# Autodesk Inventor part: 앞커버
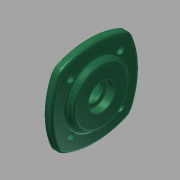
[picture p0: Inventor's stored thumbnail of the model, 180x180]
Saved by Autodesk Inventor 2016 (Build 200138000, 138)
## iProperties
Created: 2015-11
Part Number: 앞커버
Material: 일반
Document SubType Name: Modeling
Designer: mduedu
Density: 1 g/cm^3
Appearance: 매끄러움 - 짙은 바다 녹색
Mass: 112.857 g
Surface Area: 251.176 cm^2
Volume: 112.857 cm^3
Author: mduedu
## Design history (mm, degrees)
sketch "스케치1"
  geometry: L1 (50, 50)-(-50, 50); L2 (-50, 50)-(-50, -50); L3 (-50, -50)-(50, -50); L4 (50, -50)-(50, 50); L5 (0, 50)-(0, -50); L6 (50, 0)-(-50, 0); A1 r 90 centre (-40, 0) between (40.415, -40.415) and (40.415, 40.415); A2 r 90 centre (40, 0) between (-40.415, 40.415) and (-40.415, -40.415); A3 r 90 centre (0, -40) between (40.415, 40.415) and (-40.415, 40.415); A4 r 90 centre (0, 40) between (-40.415, -40.415) and (40.415, -40.415); 2 further points
  constraints: 12 end point, 8 point on circle, 5 midpoint, 4 centre point, 2 horizontal alignment, 2 parallel, 2 perpendicular, 2 symmetric about line, 2 tangent, 2 vertical alignment, 1 equal radius, 1 horizontal, 2 other
  dimensions: "d0" = 100 distance of L3.end L1.start; "d2" = 90 radius of A1
extrude "돌출1" new body sketch "스케치1" distance "d3" = 8; taper "d4" = 0 deg
sketch "스케치2"
  geometry: C1 r 35 at (0, 0); 1 further point
  constraints: 1 centre point, 1 coincident
  dimensions: "d5" = 70 diameter of C1
extrude "돌출2" join sketch "스케치2" distance "d6" = 7; taper "d7" = -30 deg
sketch "스케치3"
  geometry: L1 (0, 0)-(0, 40); L2 (0, 0)-(-28.284, 28.284); A1 r 40 centre (0, 0) between (0, 40) and (-28.284, 28.284); 2 further points
  constraints: 4 end point, 2 coincident, 2 point on circle, 1 centre point, 1 vertical
  dimensions: "d8" = 80 diameter of A1; "d9" = 45 deg angle of L1 L2
hole "구멍1" sketch "스케치3" at (-28.284, 28.284) diameter "d11" = 4.5; stored, may be unused: countersink angle "d15" = 90 deg, drill point angle "d17" = 118 deg; dims "d12" = 6, "d13" = 8, "d14" = 4.4, "d16" = 8
sketch "스케치4"
  geometry: C1 r 35 at (0, 0); 1 further point
  constraints: 1 centre point, 1 coincident
  dimensions: "d21" = 70 diameter of C1
extrude "돌출3" join sketch "스케치4" distance "d23" = 12; taper "d24" = 0 deg
hole "구멍2" diameter "d27" = 30; stored, may be unused: countersink angle "d31" = 90 deg, drill point angle "d33" = 0 deg; dims "d25" = 10, "d26" = 10, "d28" = 6, "d29" = 40, "d30" = 12, "d32" = 15
fillet "모깎기2" dims "d35" = 15
fillet "모깎기3" dims "d36" = 3
fillet "모깎기4" dims "d37" = 3
fillet "모깎기5" dims "d38" = 0.3
chamfer "모따기1" distance "d39" = 1; stored, may be unused: second distance "d40" = 2, angle "d41" = 45 deg
hole "구멍3" diameter "d44" = 20; stored, may be unused: countersink angle "d48" = 90 deg, drill point angle "d50" = 118 deg; dims "d45" = 6, "d46" = 30, "d47" = 8.7, "d49" = 8, "d55" = 10, "d56" = 10
fillet "모깎기6" dims "d51" = 0.3
chamfer "모따기2" distance "d52" = 0.7; stored, may be unused: second distance "d53" = 2, angle "d54" = 30 deg
node "솔리드1"
pattern_circular "원형 패턴1" dims angle "d19" = 360 deg
